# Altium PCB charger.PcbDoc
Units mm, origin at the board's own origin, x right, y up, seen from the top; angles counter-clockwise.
Board outline 115.3 x 46.2 mm, 2 copper layers (Top Layer, Bottom Layer); 16 components, 14 nets, 43 pads, 0 vias.
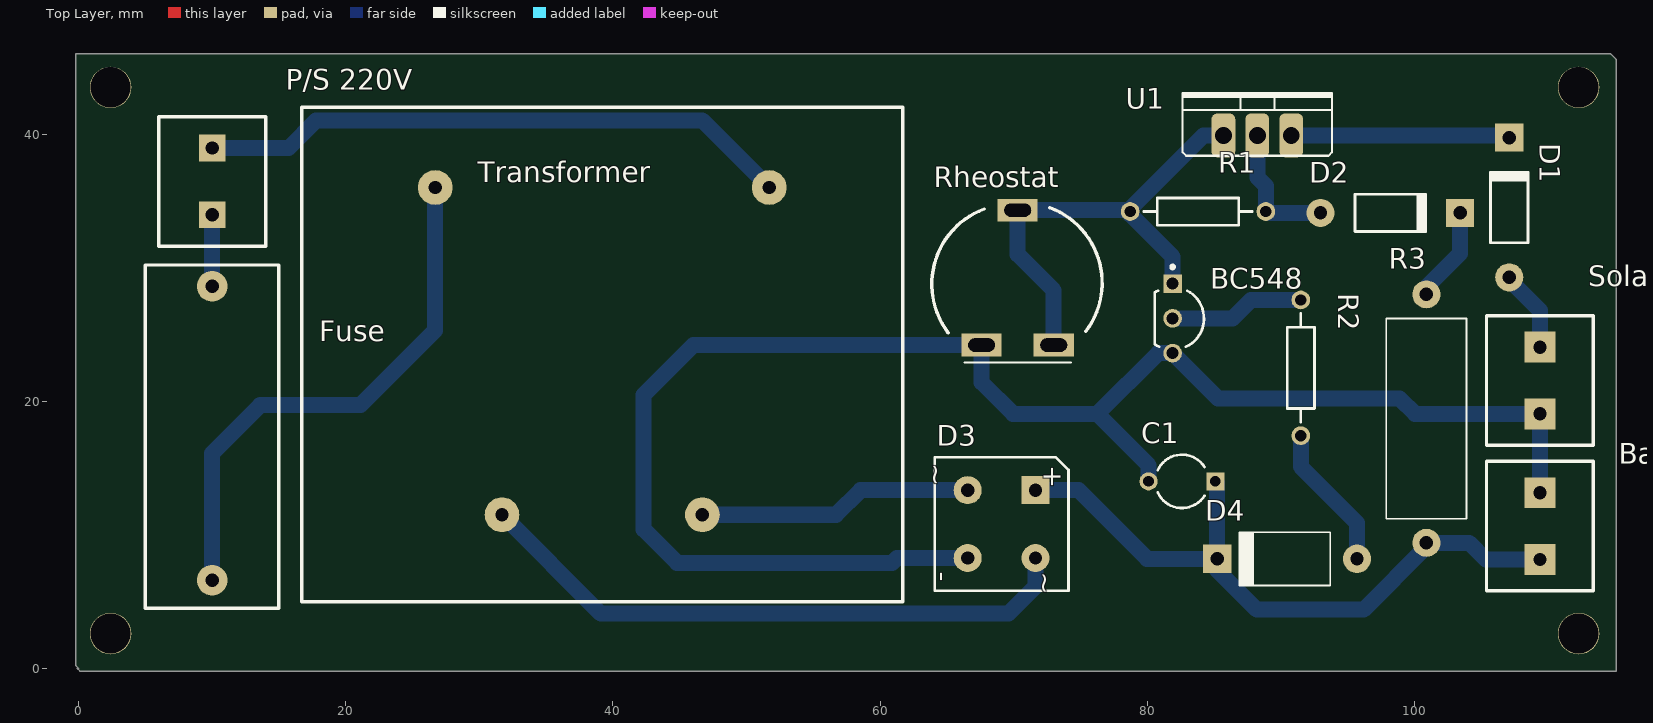
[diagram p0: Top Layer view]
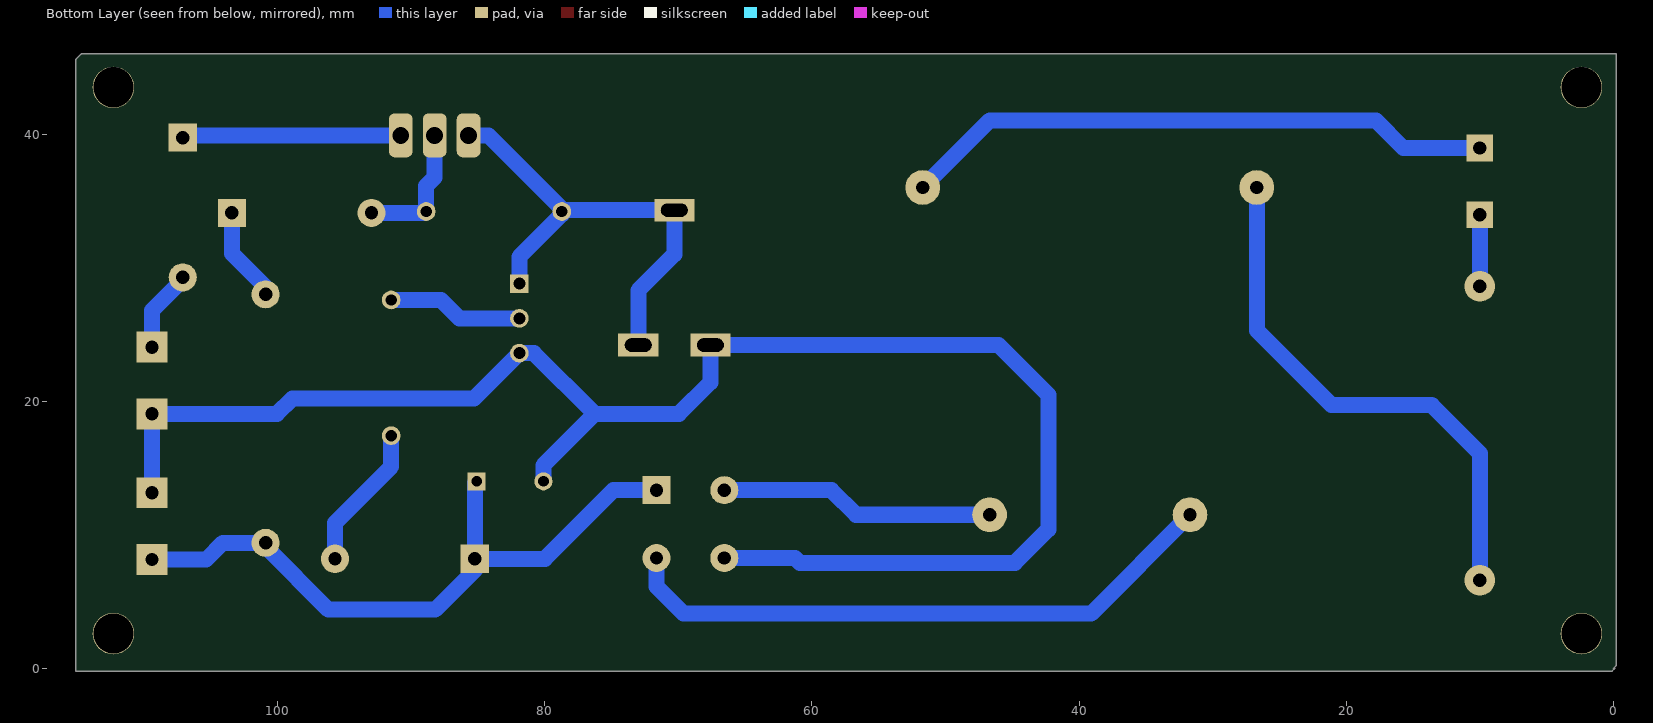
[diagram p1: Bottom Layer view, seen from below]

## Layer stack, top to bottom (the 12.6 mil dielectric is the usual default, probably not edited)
Top Solder: solder mask 0.0102, Solder Resist, Dk 3.5
Top Layer: signal copper 0.0356
Dielectric 1: dielectric 0.32, FR-4, Dk 4.8
Bottom Layer: signal copper 0.0356
Bottom Solder: solder mask 0.0102, Solder Resist, Dk 3.5

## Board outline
0,0 -0.2,0.2 -0.2,46 114.7,46 114.9,45.8 115.1,45.6 115.1,-0.2 0.1,-0.2 -0.1,0

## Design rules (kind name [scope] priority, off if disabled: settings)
Clearance 220V_clearance [InNetClass('220V')] p1: gap=3
Clearance [All] p2: gap=0.5
PolygonConnect [All] p1: connectstyle=Relief reliefconductorwidth=0.254 reliefentries=4 polygonreliefangle="90 Angle" airgapwidth=0.254
RoutingLayers [All] p1: top layer_v5=FALSE bottom layer_v5=TRUE
RoutingVias [All] p1: holewidth=0.711 width=1.27 viastyle="Through Hole" minholewidth=0.711 minwidth=1.27 maxholewidth=0.711 maxwidth=1.27
SolderMaskExpansion [All] p1: expansion=0.102
UnpouredPolygon [All] p1: allowunpoured=FALSE
Width [All] p1: maxlimit=1.5 minlimit=1 preferedwidth=1.2
28 further rules are at their usual default settings.

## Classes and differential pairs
net class 220V: NetFuse_1 NetFuse_2 "NetP/S 220V_2"
component class charger: Battery BC548 C1 D1 D2 D4 Fuse "P/S 220V" R1 R2 R3 Rheostat "Solar Panel" Transformer U1

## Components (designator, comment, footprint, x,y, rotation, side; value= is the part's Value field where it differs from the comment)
Battery "Homemade Connector" "Connector (Clamp?)"#1 113.4,5.8 r90 top
BC548 "BC548BRL1G" ONSC-TO-92-3-29-11_AM_BL 81.9,26.2 r270 top
C1 "Cap2" CAPR5-4X5 82.6,14 r180 top
D1 "Diode 1N4007" DO-41 107.1,34.5 r90 top
D2 "Diode 1N4007" DO-41 98.2,34.1 r0 top
D3 "Bridge1" D-38 69.1,10.8 r270 top
D4 "D Zener" "Zener Diode" 95.7,13.2 r180 top
Fuse "Fuse 1" "Fuse Case" 5,29.6 r270 top
"P/S 220V" "Homemade Connector" "Connector (Clamp?)"#2 14,31.6 r90 top
R1 "Res2" AXIAL-0.4 83.8,34.2 r0 top
R2 "Res2" AXIAL-0.4 91.5,22.5 r90 top
R3 "ResCustom" PCBComponent_1 97.9,26.2 r270 top
Rheostat "RPot" "potentiometer (Piher)" 66.3,23.3 r0 top
"Solar Panel" "Homemade Connector" "Connector (Clamp?)"#1 105.4,26.4 r270 top
Transformer "Trans" Transformer 16.7,5 r0 top
U1 "LM317" to220-123-v 85.7,39.9 r0 top

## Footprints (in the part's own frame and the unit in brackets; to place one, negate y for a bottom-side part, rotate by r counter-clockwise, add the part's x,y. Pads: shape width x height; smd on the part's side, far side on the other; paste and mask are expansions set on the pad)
AXIAL-0.4 [mm] "Axial Device, Thru-Hole; 2 Leads; 0.4 in Pin Spacing"
  round 1.4 hole 0.85: 1(-5.08,0) 2(5.08,0)
  silkscreen extent -4.06,-1.02 4.06,1.02
CAPR5-4X5 [mm] "Capacitor; 2 Leads"
  rect 1.35x1.35 hole 0.8: 1(-2.5,0)
  round 1.35 hole 0.8: 2(2.5,0)
  silkscreen extent -1.69,-2 1.82,2
"Connector (Clamp?)"#1 [mm]
  rect 2.3x2.3 hole 1: 1(2.35,4) 2(7.35,4)
  silkscreen extent 0,0 9.7,8
"Connector (Clamp?)"#2 [mm]
  rect 2x2 hole 1: 1(2.35,4) 2(7.35,4)
  silkscreen extent 0,0 9.7,8
D-38 [mm] "Bridge Rectifier; 4 Terminals; Body 9.4 x 9.4 mm (typ); Pitch 5.08 mm"
  rect 2.1x2.1 hole 1: 1(-2.54,2.54)
  round 2.1 hole 1: 2(-2.54,-2.54) 3(2.54,-2.54) 4(2.54,2.54)
  silkscreen extent -5,-5 5,5, body extent -5,-5 5,5, height 9.91
DO-41 [mm] "Diode, Axial; Body 5.2 x 2.7 mm (LxDia. max), Lead Dia. 0.86 mm (max)"
  round 2.1 hole 1: 1(-5.23,0)
  rect 2.1x2.1 hole 1: 2(5.23,0)
  silkscreen extent -2.65,-1.4 2.75,1.4
"Fuse Case" [mm] "Fuse Case"
  round 2.3 hole 1: 1(1,5) 2(23,5)
  silkscreen extent -0.6,0 25.1,10
ONSC-TO-92-3-29-11_AM_BL [mm] "TO, 3-Leads, Body Dia 4.7mm, Pitch 2.6mm"
  rect 1.4x1.4 hole 0.9: 1(-2.6,0)
  round 1.4 hole 0.9: 2(0,0) 3(2.6,0)
  silkscreen extent -3.97,-1.34 2.13,2.35, body extent -2.84,-1.34 2.84,2.36, height 8.92
PCBComponent_1 [mm]
  round 2.1 hole 1: 1(-1.8,3) 2(16.8,3)
  silkscreen extent 0,0 15,6
"potentiometer (Piher)" [mm]
  rect 3x1.7 hole 1 slot 2 at 0 deg: 1(1.3,0.9) 2(6.7,0.9) 3(4,11)
  silkscreen extent -2.42,-0.4 10.32,11.19
to220-123-v [mil] "TO220 123 pin numbering Vertical mount"
  rrect50% 70x130 hole 50: 1(0,0) 2(100,0) 3(200,0)
  silkscreen extent -120,-60 320,125, body extent -121,-59 321,126, height 945
Transformer [mm] "TL42S-120-416"
  round 2.6 hole 1: 1(10,31) 2(35,31) 3(15,6.5) 4(30,6.5)
  silkscreen extent 0,0 45,37
"Zener Diode" [mm] "Zener Diode 13.8"
  oval 2.1x2.14 hole 1: 1(0,5)
  rect 2.1x2.14 hole 1: 2(10.46,5)
  silkscreen extent 2,3 8.8,7

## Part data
Battery "P/S 220V" "Solar Panel": library part "Header 2", "Klema"
BC548: "Amplifier Transistor, NPN Silicon, 3-Pin TO-92, Pb-Free, Tape and Reel"
C1: "Capacitor"
D1 D2: "1 Amp General Purpose Rectifier"
D3: "Full Wave Diode Bridge"
D4: "Zener Diode"
Fuse: "Fuse"
R1 R2: "Resistor"
Rheostat: "Potentiometer"
Transformer: "Transformer TL42S-120-416"
U1: library part LM317-TO220, "LINEAR REGULATOR ADJ POSITIVE"

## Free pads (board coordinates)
  round 3.1 hole 3 unplated: 8(2.4,2.6) 8(112.3,2.6)
  round 3.1 hole 3: 8(2.4,43.5) 8(112.3,43.5)

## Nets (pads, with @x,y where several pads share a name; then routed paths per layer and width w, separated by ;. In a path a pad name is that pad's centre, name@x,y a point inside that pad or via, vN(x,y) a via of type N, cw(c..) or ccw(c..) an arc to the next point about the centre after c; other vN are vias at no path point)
GND: "Solar Panel.2" Battery.2 BC548.3 C1.2 D3.3 Rheostat.1 | length 124.2
  Bottom Layer w1.2: D3.3 61.26,8.26 60.895,7.895 44.805,7.895 42.3,10.4 42.3,20.47 46.03,24.2 Rheostat.1 67.6,21.4 69.955,19.045 76.255,19.045 ; C1.2 80.1,15.2 76.255,19.045 ; Battery.2 109.4,19.05 100.05,19.05 98.9,20.2 85.3,20.2 BC548.3 80.81,23.6 76.255,19.045
NetBattery_1: Battery.1 C1.1 D3.1 D4.2 R3.2 | length 50.6
  Bottom Layer w1.2: D3.1 74.86,13.34 80,8.2 D4.2 ; C1.1 85.24,13.86 D4.2 ; Battery.1 105.35,8.15 104.1,9.4 R3.2 100.9,9.1 96.2,4.4 88.2,4.4 85.24,7.36 D4.2
NetBC548_1: BC548.1 R1.1 Rheostat.2 Rheostat.3 U1.1 | length 35.7
  Bottom Layer w1.2: Rheostat.2 73,28.3 70.3,31 Rheostat.3 78.62,34.3 84.22,39.9 U1.1 ; R1.1 78.72,33.98 81.9,30.8 BC548.1
NetBC548_2: BC548.2 R2.2 | length 10.2
  Bottom Layer w1.2: BC548.2 86.4,26.2 87.78,27.58 R2.2
NetD1_1: "Solar Panel.1" D1.1 | length 6.2
  Bottom Layer w1.2: D1.1 107.1,29.1 109.4,26.8 109.4,24.05
NetD1_2: D1.2 U1.3 | length 16.4
  Bottom Layer w1.2: U1.3 106.93,39.9 D1.2
NetD2_1: D2.1 R1.2 U1.2 | length 10.1
  Bottom Layer w1.2: U1.2 88.24,36.76 88.88,36.12 R1.2 88.98,34.1 D2.1
NetD2_2: D2.2 R3.1 | length 7.1
  Bottom Layer w1.2: R3.1 100.9,28.54 103.43,31.07 D2.2
NetD3_2: D3.2 Transformer.4 | length 20.6
  Bottom Layer w1.2: Transformer.4 56.7,11.5 58.54,13.34 D3.2
NetD3_4: D3.4 Transformer.3 | length 46
  Bottom Layer w1.2: Transformer.3 39.1,4.1 69.6,4.1 71.64,6.14 D3.4
NetD4_1: D4.1 R2.1 | length 11
  Bottom Layer w1.2: R2.1 91.5,15.1 95.7,10.9 D4.1
NetFuse_1: "P/S 220V.1" Fuse.1 | length 5.4
  Bottom Layer w1.2: Fuse.1 10,33.95
NetFuse_2: Fuse.2 Transformer.1 | length 40.7
  Bottom Layer w1.2: Fuse.2 10,16.1 13.6,19.7 21.1,19.7 26.7,25.3 Transformer.1
"NetP/S 220V_2": "P/S 220V.2" Transformer.2 | length 44.6
  Bottom Layer w1.2: 10,38.95 15.716,38.95 17.782,41.016 46.684,41.016 Transformer.2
